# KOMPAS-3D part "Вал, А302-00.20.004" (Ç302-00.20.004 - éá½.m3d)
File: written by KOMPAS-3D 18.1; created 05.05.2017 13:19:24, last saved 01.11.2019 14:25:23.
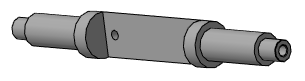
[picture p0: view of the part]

Document properties: Автор: Милов; Организация: Милов; Полное имя файла: D:\Мембранные насосы\Мембранный электропривод\А302-00.00.000 - ASTRA-302 (МЭ200)\3Д\А302-00.20.004 - Вал.m3d

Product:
- Part/product: Вал  | designation А302-00.20.004
    Материал: Сталь 40Х  ГОСТ 4543-71 (density 7825 kg/m3)
    Масса: 0.363087
    Раздел спецификации: Детали
    Форматы листов документа: A3
- Part/product: Вал  | designation А302-02.20.004
    Материал: Сталь 40Х  ГОСТ 4543-71 (density 7825 kg/m3)
    Масса: 0.365977
    Раздел спецификации: Детали
    Форматы листов документа: A3
    source file: ..\Чертежи ПВХ\А302-02.20.004 - Вал.cdw
- Part/product: Вал  | designation А302-04.20.004
    Материал: Сталь 40Х  ГОСТ 4543-71 (density 7825 kg/m3)
    Масса: 0.49487
    Раздел спецификации: Детали
    Форматы листов документа: A3
    source file: ..\А302-04.00.000 - Мембранный насос ASTRA-302-PP\А302-04.20.004 - Вал.cdw, ..\Чертежи ПВХ\А302-03.20.004 - Вал.cdw

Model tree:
1. Эскиз:1
2. Операция вращения:1
     Угол 1 = 360
3. Эскиз:3  (with: Операция вращения:1)
4. Вырезать элемент выдавливания:1
     Расстояние 1 = 24
5. Отверстие:1  (with: Операция вращения:1)  (labels: M8)
     Глубина выреза = 15; Диаметр отверстия = 6.64684; Угол конуса торца = 118
6. M8  (with: Операция вращения:1)  (labels: cil0_24705-2004 coarse)
     Длина резьбы = 12; Шаг резьбы = 1.25; Номинальный диаметр резьбы = 8
7. Фаска:1  (with: Отверстие:1)
     Угол = 45; Длина 1 = 0.5; Длина 2 = 0.5
8. Зеркальный массив:1
9. Экземпляр ( 1 )
10. Экземпляр ( 2 )  (with: Отверстие:1)
11. M4  (with: Операция вращения:1, Фаска:1)  (labels: cil0_24705-2004 coarse)
     Длина резьбы = 12; Шаг резьбы = 1.25; Номинальный диаметр резьбы = 8
12. Эскиз:4  (with: Вырезать элемент выдавливания:1)
13. Отверстие:2  (with: Вырезать элемент выдавливания:1)
     Глубина выреза = 7.5; Диаметр отверстия = 5.1; Угол конуса торца = 118; Координата X = -34
14. M3  (labels: cil0_24705-2004 coarse)
     Длина резьбы = 6; Шаг резьбы = 0.5; Номинальный диаметр резьбы = 3
15. Фаска:2  (with: Операция вращения:1)
     Угол = 45; Длина 1 = 0.3; Длина 2 = 0.3
16. Смещенная плоскость:1
     Расстояние = 10
17. Эскиз:5
18. Вырезать элемент выдавливания:2
     Расстояние 2 = 1.5
19. Зеркальный массив:2  (with: Экземпляр ( 1 ), Экземпляр ( 2 ), Отверстие:2, Вырезать элемент выдавливания:2)
20. Эскиз:6
21. Вырезать элемент выдавливания:3  (labels: Сталь 40Х  ГОСТ 4543-71)
     Расстояние 1 = 1
22. Смещенная плоскость:2  (with: Операция вращения:1)
     Расстояние = 56.5
23. Эскиз:9  (with: Операция вращения:1)
24. Элемент выдавливания:2
     Расстояние 1 = 17; Расстояние 2 = 10
25. Элемент выдавливания:3
     Расстояние 2 = 10
26. Эскиз:10
27. Элемент выдавливания:5
     Расстояние 1 = 14; Расстояние 2 = 14
28. Зеркальный массив:3
29. Экземпляр ( 1 )
30. Экземпляр ( 2 )  (with: Элемент выдавливания:3, Элемент выдавливания:2, Элемент выдавливания:5)
31. Элемент выдавливания:6
     Расстояние 1 = 14; Расстояние 2 = 14
32. Элемент выдавливания:7  (with: Элемент выдавливания:2)
     Расстояние 1 = 49
33. Эскиз:11  (with: Элемент выдавливания:2)
34. Элемент выдавливания:8  (with: Операция вращения:1)
     Расстояние 1 = 0.5
35. Элемент выдавливания:9  (with: Операция вращения:1)
     Расстояние 1 = 0.5
36. Элемент выдавливания:12  (with: Элемент выдавливания:2)
     Расстояние 1 = 0.5
37. Элемент выдавливания:13  (with: Элемент выдавливания:2)  (labels: Сталь 40Х  ГОСТ 4543-71)
     Расстояние 1 = 0.5

Expressions: 13.5/2

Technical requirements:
  Gost Type A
